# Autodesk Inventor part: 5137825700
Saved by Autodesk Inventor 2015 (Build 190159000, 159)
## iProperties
Created: 2020-07
Part Number: 5137825700
Checked By: TraceParts S.A.
Material: Generic
Catalog Web Link: www.traceparts.com
Document SubType Name: Modeling
Designer: TraceParts
Density: 1 g/cm^3
Appearance: Default
Company: TraceParts S.A.
Author: TraceParts
REFERENCE: 5137825700
DESIGN: CVAB/4-4000/400 N D 0,56KW (230V) 50Hz - 5137825700
SUPPLIER: Soler & Palau
TraceParts.PartNumber: 10-14122018-105188
TraceParts.PartTitle: CVAT-N
TraceParts.InstanceId: 10-14122018-1051887ZNVV4GRQIMJ9V4YBB4S1F9QU
TraceParts.PartStatus: Published
TraceParts.PartVersion: 1.0.4
TRACEPARTS: TRACEPARTS
TraceParts.PartLanguage: en
TraceParts.ClassPath: SOLER_PALAU:10-14122018-105188
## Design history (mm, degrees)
feature "5137825700"
body "Solid1"
